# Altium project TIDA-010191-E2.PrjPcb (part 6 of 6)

## Sheet TIDA-010191-E2_USB.SchDoc: FT4232HQ_USB
size 558 x 431 mm; Date: Not shown in title block; ApprovedBy: Not shown in title block; CheckedBy: Not shown in title block; Author: Not shown in title block; CompanyName: Not shown in title block; DrawnBy: Avinash N; Engineer: Not shown in title block; Organization: Not shown in title block; Address1: Not shown in title block; Address2: Not shown in title block; Address3: Not shown in title block; Address4: Not shown in title block; DocumentNumber: 8; Revision: Use project parameter SCH_Rev; SheetNumber: 8; SheetTotal: 9; PageSetup: Record=PageOptions¦CenterHorizontal=True¦CenterVertical=True¦PrintScale=1.00¦XCorrection=1.00¦YCorrection=1.00¦PrintKind=0¦BorderSize=5000000¦LeftOffset=0¦BottomOffset=0¦Orientation=2¦PaperLength=1000¦PaperWidth=1000¦Scale=100¦PaperSource=15¦PrintQuality=600¦MediaType=1¦DitherType=10¦PaperKind=Letter¦PrintScaleMode=1
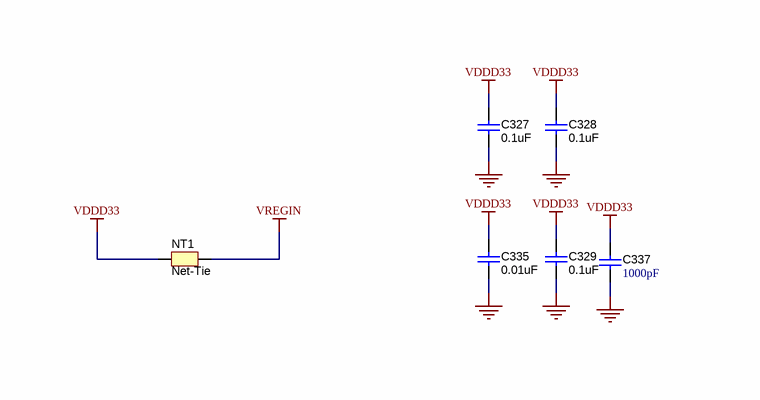
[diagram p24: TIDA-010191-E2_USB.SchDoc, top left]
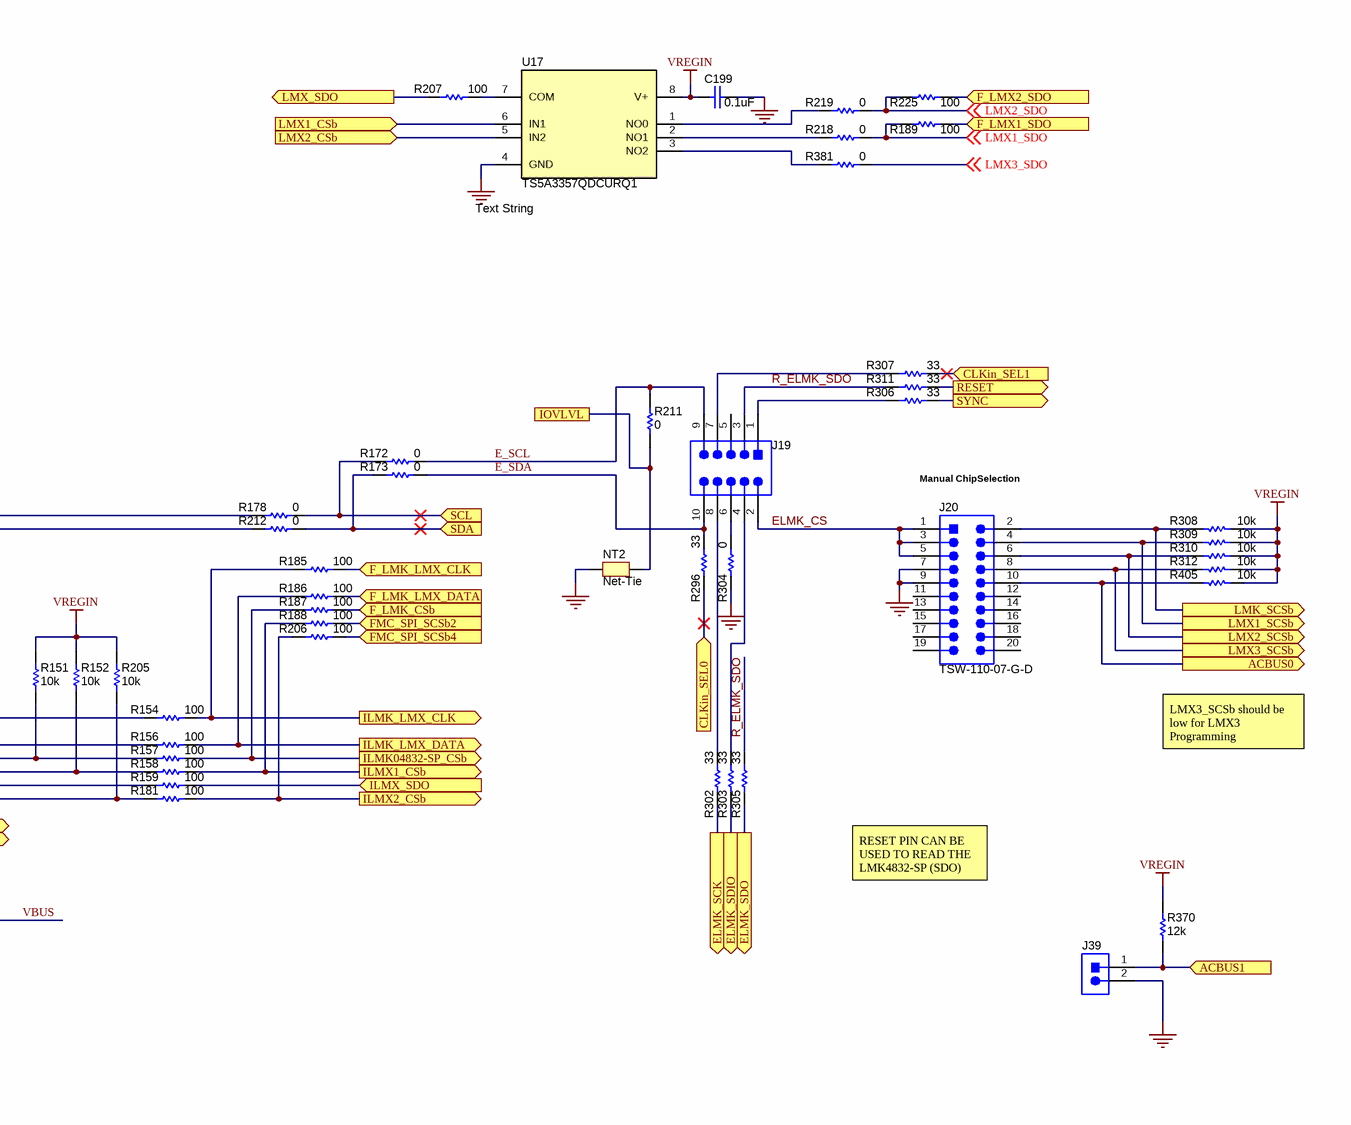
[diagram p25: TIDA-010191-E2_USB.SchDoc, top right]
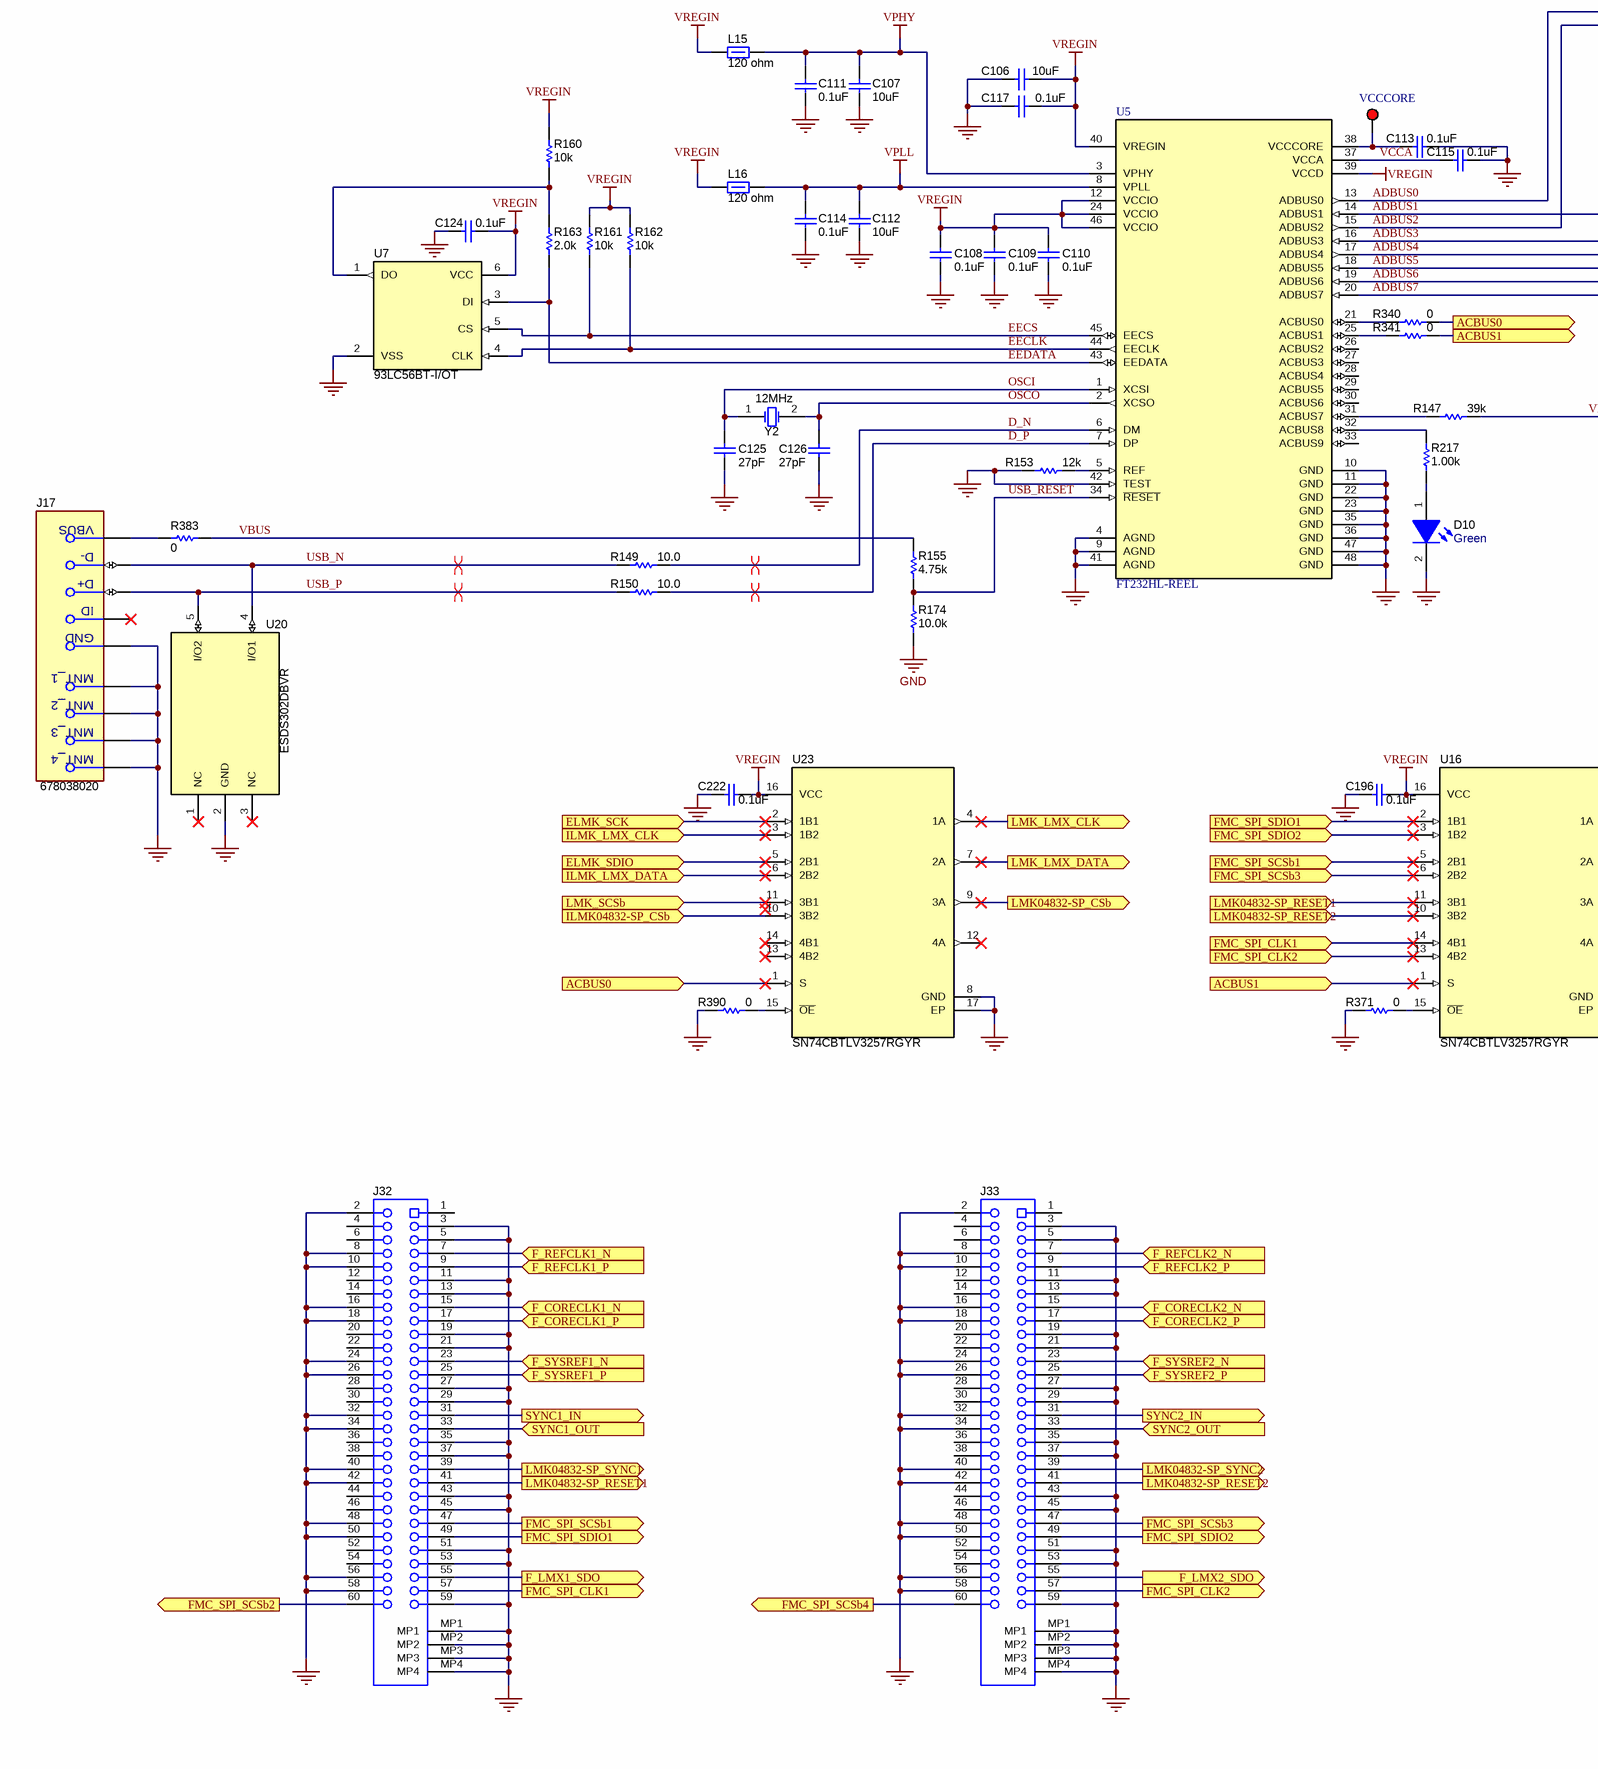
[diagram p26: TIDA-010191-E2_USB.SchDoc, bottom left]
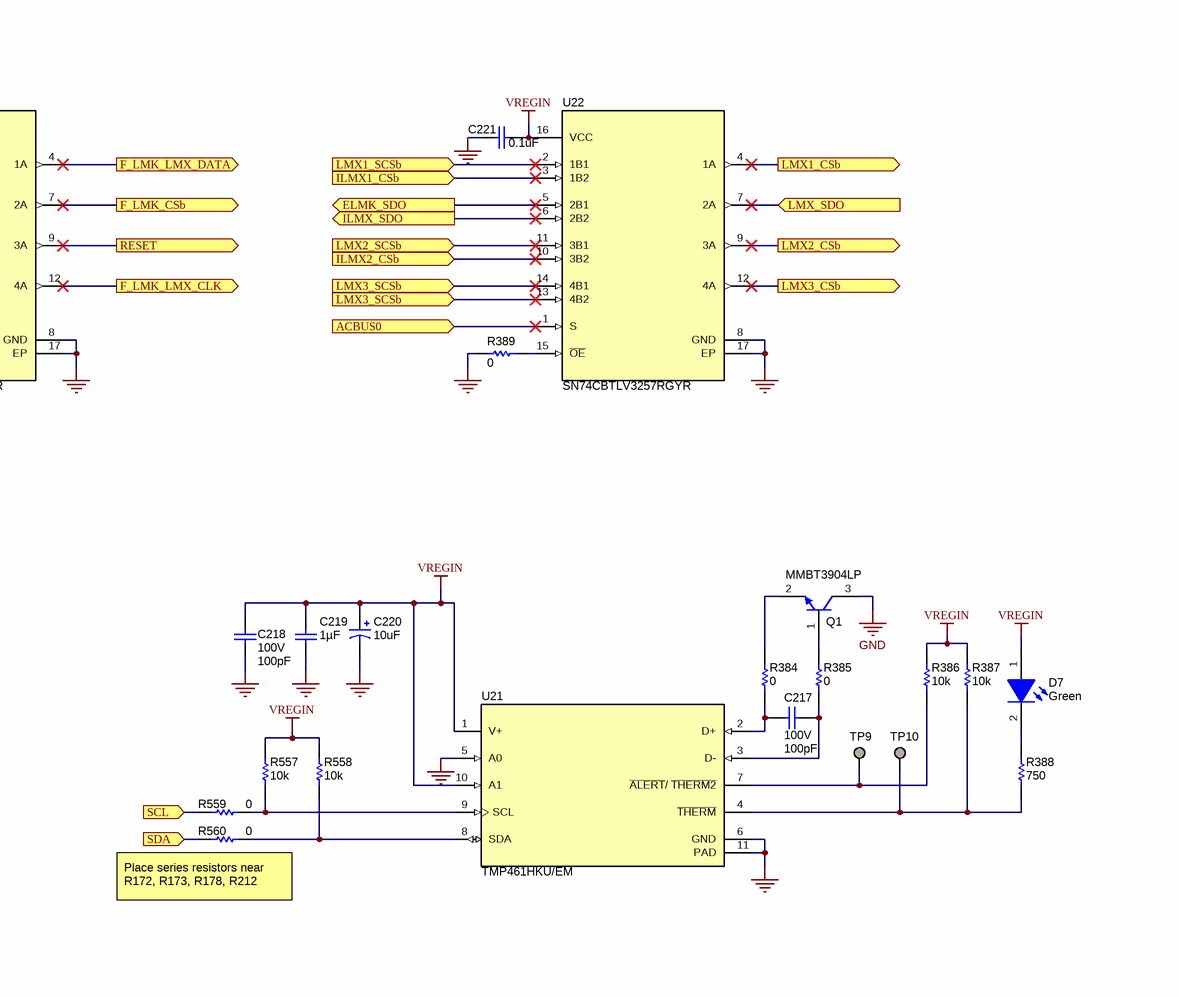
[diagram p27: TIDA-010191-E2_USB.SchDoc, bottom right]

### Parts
C106  ValueDisplayed: 10uF  [0603]  (hidden comment: CMP-0007003-5)
C107  ValueDisplayed: 10uF  [0603]  (hidden comment: CMP-0007003-5)
C108  ValueDisplayed: 0.1uF  [0603]  (hidden comment: Capacitor)
C109  ValueDisplayed: 0.1uF  [0603]  (hidden comment: Capacitor)
C110  ValueDisplayed: 0.1uF  [0603]  (hidden comment: Capacitor)
C111  ValueDisplayed: 0.1uF  [0603]  (hidden comment: Capacitor)
C112  ValueDisplayed: 10uF  [0603]  (hidden comment: CMP-0007003-5)
C113  ValueDisplayed: 0.1uF  [0603]  (hidden comment: Capacitor)
C114  ValueDisplayed: 0.1uF  [0603]  (hidden comment: Capacitor)
C115  ValueDisplayed: 0.1uF  [0603]  (hidden comment: Capacitor)
C117  ValueDisplayed: 0.1uF  [0603]  (hidden comment: Capacitor)
C124  ValueDisplayed: 0.1uF  [0603]  (hidden comment: Capacitor)
C125  ValueDisplayed: 27pF  [0603]  (hidden comment: Capacitor)
C126  ValueDisplayed: 27pF  [0603]  (hidden comment: Capacitor)
C196  value 0.1uF  [0603]  (hidden comment: C0603C104J3RACTU)
C199  ValueDisplayed: 0.1uF  [0603]  (hidden comment: Capacitor)
C217  VDC_V: 100V  ValueDisplayed: 100pF  [0603]  (hidden comment: GCM1885C2A101JA16D)
C218  VDC_V: 100V  ValueDisplayed: 100pF  [0603]  (hidden comment: GCM1885C2A101JA16D)
C219  ValueDisplayed: 1µF  [0603]  (hidden comment: 0603YD105KAT2A)
C220  ValueDisplayed: 10uF  [3528-21]  (hidden comment: 293D106X0010B2TE3)
C221  value 0.1uF  [0603]  (hidden comment: C0603C104J3RACTU)
C222  value 0.1uF  [0603]  (hidden comment: C0603C104J3RACTU)
C327  ValueDisplayed: 0.1uF  [0603]  (hidden comment: Capacitor)
C328  ValueDisplayed: 0.1uF  [0603]  (hidden comment: Capacitor)
C329  ValueDisplayed: 0.1uF  [0603]  (hidden comment: Capacitor)
C335  ValueDisplayed: 0.01uF  [0603]  (hidden comment: Capacitor)
C337  ValueDisplayed: 1000pF  [0805_HV]  (hidden comment: Capacitor)
D7  value Green  [LTST-C191_Green]  (hidden comment: LTST-C191KGKT)
D10  value Green  [LTST-C191_Green]  (hidden comment: LED)
J17  678038020  [FP-678038020_CONN_USB-MFG]
J19  CMP-0055434-2  [FCI_52601-S10-8LF]  (value not drawn)
J20  TSW-110-07-G-D  [TSW-110-07-G-D]
J32  CMP-0075524-1  [Samtec_QSH-030-01-X-D-A]  (value not drawn)
J33  CMP-0075524-1  [Samtec_QSH-030-01-X-D-A]  (value not drawn)
J39  HTSW-102-07-G-S  [Samtec_HTSW-102-07-G-S]  (value not drawn)
L15  ValueDisplayed: 120 ohm  [1206]  (hidden comment: Ferrite_Bead)
L16  ValueDisplayed: 120 ohm  [1206]  (hidden comment: Ferrite_Bead)
NT1  Net-Tie  [Net-Tie_0805_HV_NoOverlay]  (net tie, no BOM)
NT2  Net-Tie  [Net-Tie_0805_HV_NoOverlay]  (net tie, no BOM)
Q1  MMBT3904LP  [DIODES_X1-DFN1006-3]
R147  ValueDisplayed: 39k  [0603]  (hidden comment: Resistor)
R149  ValueDisplayed: 10.0  [0603]  (hidden comment: Resistor)
R150  ValueDisplayed: 10.0  [0603]  (hidden comment: Resistor)
R151  ValueDisplayed: 10k  [0603]  (hidden comment: Resistor)
R152  ValueDisplayed: 10k  [0603]  (hidden comment: Resistor)
R153  ValueDisplayed: 12k  [0603]  (hidden comment: CMP-0025711-4)
R154  ValueDisplayed: 100  [0603]  (hidden comment: CMP-0021991-4)
R155  ValueDisplayed: 4.75k  [0402]  (hidden comment: CRCW04024K75FKED)
R156  ValueDisplayed: 100  [0603]  (hidden comment: CMP-0021991-4)
R157  ValueDisplayed: 100  [0603]  (hidden comment: CMP-0021991-4)
R158  ValueDisplayed: 100  [0603]  (hidden comment: CMP-0021991-4)
R159  ValueDisplayed: 100  [0603]  (hidden comment: CMP-0021991-4)
R160  ValueDisplayed: 10k  [0603]  (hidden comment: Resistor)
R161  ValueDisplayed: 10k  [0603]  (hidden comment: Resistor)
R162  ValueDisplayed: 10k  [0603]  (hidden comment: Resistor)
R163  ValueDisplayed: 2.0k  [0603]  (hidden comment: Resistor)
R172  ValueDisplayed: 0  [0402]  (hidden comment: Resistor)
R173  ValueDisplayed: 0  [0402]  (hidden comment: Resistor)
R174  ValueDisplayed: 10.0k  [0402]  (hidden comment: CRCW040210K0FKED)
R178  ValueDisplayed: 0  [0603]  (hidden comment: Resistor)
R181  ValueDisplayed: 100  [0603]  (hidden comment: CMP-0021991-4)
R185  ValueDisplayed: 100  [0603]  (hidden comment: CMP-0021991-4)
R186  ValueDisplayed: 100  [0603]  (hidden comment: CMP-0021991-4)
R187  ValueDisplayed: 100  [0603]  (hidden comment: CMP-0021991-4)
R188  ValueDisplayed: 100  [0603]  (hidden comment: CMP-0021991-4)
R189  ValueDisplayed: 100  [0603]  (hidden comment: CMP-0021991-4)
R205  ValueDisplayed: 10k  [0603]  (hidden comment: Resistor)
R206  ValueDisplayed: 100  [0603]  (hidden comment: CMP-0021991-4)
R207  ValueDisplayed: 100  [0603]  (hidden comment: CMP-0021991-4)
R211  ValueDisplayed: 0  [0603]  (hidden comment: Resistor)
R212  ValueDisplayed: 0  [0603]  (hidden comment: Resistor)
R217  ValueDisplayed: 1.00k  [0603]  (hidden comment: Resistor)
R218  ValueDisplayed: 0  [0402]  (hidden comment: Resistor)
R219  ValueDisplayed: 0  [0402]  (hidden comment: Resistor)
R225  ValueDisplayed: 100  [0603]  (hidden comment: CMP-0021991-4)
R296  ValueDisplayed: 33  [0603]  (hidden comment: Resistor)
R302  ValueDisplayed: 33  [0603]  (hidden comment: Resistor)
R303  ValueDisplayed: 33  [0603]  (hidden comment: Resistor)
R304  ValueDisplayed: 0  [0603]  (hidden comment: Resistor)
R305  ValueDisplayed: 33  [0603]  (hidden comment: Resistor)
R306  ValueDisplayed: 33  [0603]  (hidden comment: Resistor)
R307  ValueDisplayed: 33  [0603]  (hidden comment: Resistor)
R308  ValueDisplayed: 10k  [0603]  (hidden comment: Resistor)
R309  ValueDisplayed: 10k  [0603]  (hidden comment: Resistor)
R310  ValueDisplayed: 10k  [0603]  (hidden comment: Resistor)
R311  ValueDisplayed: 33  [0603]  (hidden comment: Resistor)
R312  ValueDisplayed: 10k  [0603]  (hidden comment: Resistor)
R340  ValueDisplayed: 0  [0402]  (hidden comment: Resistor)
R341  ValueDisplayed: 0  [0402]  (hidden comment: Resistor)
R370  ValueDisplayed: 12k  [0402]  (hidden comment: Resistor)
R371  ValueDisplayed: 0  [0402]  (hidden comment: Resistor)
R381  ValueDisplayed: 0  [0402]  (hidden comment: Resistor)
R383  ValueDisplayed: 0  [0603]  (hidden comment: CRCW06030000Z0EA)
R384  ValueDisplayed: 0  [0805_HV]  (hidden comment: ERJ-6GEY0R00V)
R385  ValueDisplayed: 0  [0805_HV]  (hidden comment: ERJ-6GEY0R00V)
R386  ValueDisplayed: 10k  [0805_HV]  (hidden comment: CRCW080510K0JNEA)
R387  ValueDisplayed: 10k  [0805_HV]  (hidden comment: CRCW080510K0JNEA)
R388  ValueDisplayed: 750  [0805_HV]  (hidden comment: CRCW0805750RJNEA)
R389  ValueDisplayed: 0  [0402]  (hidden comment: CMP-0026822-3)
R390  ValueDisplayed: 0  [0402]  (hidden comment: Resistor)
R405  ValueDisplayed: 10k  [0603]  (hidden comment: Resistor)
R557  ValueDisplayed: 10k  [0805_HV]  (hidden comment: CRCW080510K0JNEA)
R558  ValueDisplayed: 10k  [0805_HV]  (hidden comment: CRCW080510K0JNEA)
R559  ValueDisplayed: 0  [0603]  (hidden comment: Resistor)
R560  ValueDisplayed: 0  [0603]  (hidden comment: Resistor)
TP9  1573-2  [Keystone1573-2]  (value not drawn)
TP10  1573-2  [Keystone1573-2]  (value not drawn)
U5  FT232HL-REEL  [LQFP-48_N]
U7  93LC56BT-I/OT  [SOT-23-6]
U16  SN74CBTLV3257RGYR  [RGY0016A]
U17  TS5A3357QDCURQ1  [DCU0008A_N]
U20  ESDS302DBVR  [DBV0005A_N]
U21  TMP461HKU/EM  [HKU0010_CUSTOM_A]
U22  SN74CBTLV3257RGYR  [RGY0016A]
U23  SN74CBTLV3257RGYR  [RGY0016A]
VCCCORE  5000  [Keystone5000]  (value not drawn)
Y2  Frequency_Fixed: 12MHz  [XTAL_ABM3]  (hidden comment: ABM3-12.000MHZ-D2Y-T)

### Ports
ACBUS0 (in), ACBUS0 (out), ACBUS1 (in), ACBUS1 (out), CLKin_SEL0 (in), CLKin_SEL1 (in), ELMK_SCK (in), ELMK_SCK (out), ELMK_SDIO (in), ELMK_SDIO (out), ELMK_SDO (out), F_CORECLK1_N (in), F_CORECLK1_P (in), F_CORECLK2_N (in), F_CORECLK2_P (in), F_LMK_CSb (in), F_LMK_CSb (out), F_LMK_LMX_CLK (in), F_LMK_LMX_CLK (out), F_LMK_LMX_DATA (in), F_LMK_LMX_DATA (out), F_LMX1_SDO (in), F_LMX1_SDO (out), F_LMX2_SDO (in), F_LMX2_SDO (out), F_REFCLK1_N (in), F_REFCLK1_P (in), F_REFCLK2_N (in), F_REFCLK2_P (in), F_SYSREF1_N (in), F_SYSREF1_P (in), F_SYSREF2_N (in), F_SYSREF2_P (in), FMC_SPI_CLK1 (in), FMC_SPI_CLK1 (out), FMC_SPI_CLK2 (in), FMC_SPI_CLK2 (out), FMC_SPI_SCSb1 (in), FMC_SPI_SCSb1 (out), FMC_SPI_SCSb2 (in), FMC_SPI_SCSb2 (out), FMC_SPI_SCSb3 (in), FMC_SPI_SCSb3 (out), FMC_SPI_SCSb4 (in), FMC_SPI_SCSb4 (out), FMC_SPI_SDIO1 (in), FMC_SPI_SDIO1 (out), FMC_SPI_SDIO2 (in), FMC_SPI_SDIO2 (out), ILMK04832-SP_CSb (in), ILMK04832-SP_CSb (out), ILMK_LMX_CLK (in), ILMK_LMX_CLK (out), ILMK_LMX_DATA (in), ILMK_LMX_DATA (out), ILMX1_CSb (in), ILMX1_CSb (out), ILMX2_CSb (in), ILMX2_CSb (out), ILMX_SDO (in), ILMX_SDO (out), IOVLVL, LMK04832-SP_CSb (out), LMK04832-SP_RESET1 (in), LMK04832-SP_RESET1 (out), LMK04832-SP_RESET2 (in), LMK04832-SP_RESET2 (out), LMK04832-SP_SYNC1 (out), LMK04832-SP_SYNC2 (out), LMK_LMX_CLK (out), LMK_LMX_DATA (out), LMK_SCSb (in), LMK_SCSb (out), LMX1_CSb (in), LMX1_CSb (out), LMX1_SCSb (in), LMX1_SCSb (out), LMX2_CSb (in), LMX2_CSb (out), LMX2_SCSb (in), LMX2_SCSb (out), LMX3_CSb (out), LMX3_SCSb (in), LMX3_SCSb (out), LMX_SDO (in), LMX_SDO (out), RESET (out), SCL (in), SDA (in), SYNC1_IN (out), SYNC1_OUT (in), SYNC2_IN (out), SYNC2_OUT (in), SYNC (out)

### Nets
GND: C106.2 C107.2 C108.2 C109.2 C110.2 C111.2 C112.2 C113.1 C114.2 C115.1 C117.2 C124.1 C125.1 C126.2 C196.2 C199.2 C218.2 C219.2 C220.2(-) C221.2 C222.2 C327.2 C328.2 C329.2 C335.2 C337.2 D10.2(K) J17.5(GND) J17.6(MNT_1) J17.7(MNT_2) J17.8(MNT_3) J17.9(MNT_4) J20.7 J20.9 J32.2 J32.3 J32.5 J32.8 J32.10 J32.11 J32.13 J32.16 J32.18 J32.19 J32.21 J32.24 J32.26 J32.27 J32.29 J32.32 J32.34 J32.35 J32.37 J32.40 J32.42 J32.43 J32.45 J32.48 J32.50 J32.51 J32.53 J32.56 J32.58 J32.59 J32.MP1 J32.MP2 J32.MP3 J32.MP4 J33.2 J33.3 J33.5 J33.8 J33.10 J33.11 J33.13 J33.16 J33.18 J33.19 J33.21 J33.24 J33.26 J33.27 J33.29 J33.32 J33.34 J33.35 J33.37 J33.40 J33.42 J33.43 J33.45 J33.48 J33.50 J33.51 J33.53 J33.56 J33.58 J33.59 J33.MP1 J33.MP2 J33.MP3 J33.MP4 J39.2 NT2.2 Q1.3(C) R153.2 R174.1 R304.1 R371.1 R389.1 R390.1 U5.4(AGND) U5.9(AGND) U5.10(GND) U5.11(GND) U5.22(GND) U5.23(GND) U5.35(GND) U5.36(GND) U5.41(AGND) U5.42(TEST) U5.47(GND) U5.48(GND) U7.2(VSS) U16.8(GND) U16.17(EP) U17.4(GND) U20.2(GND) U21.5(A0) U21.6(GND) U21.11(PAD) U22.8(GND) U22.17(EP) U23.8(GND) U23.17(EP)
VDDD33: C327.1 C328.1 C329.1 C335.1 C337.1 NT1.1
VPHY: C107.1 C111.1 L15.2 U5.3(VPHY)
VPLL: C112.1 C114.1 L16.2 U5.8(VPLL)
VREGIN: C106.1 C108.1 C109.1 C110.1 C117.1 C124.2 C196.1 C199.1 C218.1 C219.1 C220.1(+) C221.1 C222.1 D7.1(A) L15.1 L16.1 NT1.2 R151.2 R152.2 R160.2 R161.2 R162.2 R205.2 R308.1 R309.1 R310.1 R312.1 R370.2 R386.2 R387.2 R405.1 R557.2 R558.2 U5.12(VCCIO) U5.24(VCCIO) U5.39(VCCD) U5.40(VREGIN) U5.46(VCCIO) U7.6(VCC) U16.16(VCC) U17.8(V+) U21.1(V+) U21.10(A1) U22.16(VCC) U23.16(VCC)
ACBUS0: J20.10 R340.1 R405.2 U22.1(S) U23.1(S) ; port ACBUS0
ACBUS1: J39.1 R341.1 R370.1 U16.1(S) ; port ACBUS1
ADBUS0: R178.1 U5.13(ADBUS0)
ADBUS1: R154.1 U5.14(ADBUS1)
ADBUS2: R212.1 U5.15(ADBUS2)
ADBUS3: R156.1 U5.16(ADBUS3)
ADBUS4: R151.1 R157.1 U5.17(ADBUS4)
ADBUS5: R152.1 R158.1 U5.18(ADBUS5)
ADBUS6: R159.1 U5.19(ADBUS6)
ADBUS7: R181.1 R205.1 U5.20(ADBUS7)
CLKin_SEL0: R296.2 ; port CLKin_SEL0
CLKin_SEL1: R307.1 ; port CLKin_SEL1
D_N: R149.2 U5.6(DM)
D_P: R150.2 U5.7(DP)
E_SCL: J19.9 R172.2 R211.1
E_SDA: J19.10 R173.2 R296.1
EECLK: R162.1 U5.44(EECLK) U7.4(CLK)
EECS: R161.1 U5.45(EECS) U7.5(CS)
EEDATA: R163.1 U5.43(EEDATA) U7.3(DI)
ELMK_CS: J19.2 J20.1 J20.3 J20.5
ELMK_SCK: R302.1 U23.2(1B1) ; port ELMK_SCK
ELMK_SDIO: R303.1 U23.5(2B1) ; port ELMK_SDIO
ELMK_SDO: R305.1 U22.5(2B1) ; port ELMK_SDO
F_CORECLK1_N: J32.15 ; port F_CORECLK1_N
F_CORECLK1_P: J32.17 ; port F_CORECLK1_P
F_CORECLK2_N: J33.15 ; port F_CORECLK2_N
F_CORECLK2_P: J33.17 ; port F_CORECLK2_P
F_LMK_CSb: R187.2 U16.7(2A) ; port F_LMK_CSb
F_LMK_LMX_CLK: R185.2 U16.12(4A) ; port F_LMK_LMX_CLK
F_LMK_LMX_DATA: R186.2 U16.4(1A) ; port F_LMK_LMX_DATA
F_LMX1_SDO: J32.55 R189.1 ; port F_LMX1_SDO
F_LMX2_SDO: J33.55 R225.1 ; port F_LMX2_SDO
F_REFCLK1_N: J32.7 ; port F_REFCLK1_N
F_REFCLK1_P: J32.9 ; port F_REFCLK1_P
F_REFCLK2_N: J33.7 ; port F_REFCLK2_N
F_REFCLK2_P: J33.9 ; port F_REFCLK2_P
F_SYSREF1_N: J32.23 ; port F_SYSREF1_N
F_SYSREF1_P: J32.25 ; port F_SYSREF1_P
F_SYSREF2_N: J33.23 ; port F_SYSREF2_N
F_SYSREF2_P: J33.25 ; port F_SYSREF2_P
FMC_SPI_CLK1: J32.57 U16.14(4B1) ; port FMC_SPI_CLK1
FMC_SPI_CLK2: J33.57 U16.13(4B2) ; port FMC_SPI_CLK2
FMC_SPI_SCSb1: J32.47 U16.5(2B1) ; port FMC_SPI_SCSb1
FMC_SPI_SCSb2: J32.60 R188.2 ; port FMC_SPI_SCSb2
FMC_SPI_SCSb3: J33.47 U16.6(2B2) ; port FMC_SPI_SCSb3
FMC_SPI_SCSb4: J33.60 R206.2 ; port FMC_SPI_SCSb4
FMC_SPI_SDIO1: J32.49 U16.2(1B1) ; port FMC_SPI_SDIO1
FMC_SPI_SDIO2: J33.49 U16.3(1B2) ; port FMC_SPI_SDIO2
ILMK04832-SP_CSb: R157.2 R187.1 U23.10(3B2) ; port ILMK04832-SP_CSb
ILMK_LMX_CLK: R154.2 R185.1 U23.3(1B2) ; port ILMK_LMX_CLK
ILMK_LMX_DATA: R156.2 R186.1 U23.6(2B2) ; port ILMK_LMX_DATA
ILMX1_CSb: R158.2 R188.1 U22.3(1B2) ; port ILMX1_CSb
ILMX2_CSb: R181.2 R206.1 U22.10(3B2) ; port ILMX2_CSb
ILMX_SDO: R159.2 U22.6(2B2) ; port ILMX_SDO
IOVLVL: NT2.1 R211.2 ; port IOVLVL
LMK04832-SP_CSb: U23.9(3A) ; port LMK04832-SP_CSb
LMK04832-SP_RESET1: J32.41 U16.11(3B1) ; port LMK04832-SP_RESET1
LMK04832-SP_RESET2: J33.41 U16.10(3B2) ; port LMK04832-SP_RESET2
LMK04832-SP_SYNC1: J32.39 ; port LMK04832-SP_SYNC1
LMK04832-SP_SYNC2: J33.39 ; port LMK04832-SP_SYNC2
LMK_LMX_CLK: U23.4(1A) ; port LMK_LMX_CLK
LMK_LMX_DATA: U23.7(2A) ; port LMK_LMX_DATA
LMK_SCSb: J20.2 R308.2 U23.11(3B1) ; port LMK_SCSb
LMX1_CSb: U17.6(IN1) U22.4(1A) ; port LMX1_CSb
LMX1_SCSb: J20.4 R309.2 U22.2(1B1) ; port LMX1_SCSb
LMX1_SDO: R189.2 R218.2 ; off-sheet LMX1_SDO
LMX2_CSb: U17.5(IN2) U22.9(3A) ; port LMX2_CSb
LMX2_SCSb: J20.6 R310.2 U22.11(3B1) ; port LMX2_SCSb
LMX2_SDO: R219.2 R225.2 ; off-sheet LMX2_SDO
LMX3_CSb: U22.12(4A) ; port LMX3_CSb
LMX3_SCSb: J20.8 R312.2 U22.13(4B2) U22.14(4B1) ; port LMX3_SCSb
LMX3_SDO: R381.2 ; off-sheet LMX3_SDO
LMX_SDO: R207.2 U22.7(2A) ; port LMX_SDO
OSCI: C125.2 U5.1(XCSI) Y2.1(OSC1)
OSCO: C126.1 U5.2(XCSO) Y2.2(OSC2)
R_ELMK_SDO: J19.3 R305.2 R311.2
RESET: R311.1 U16.9(3A) ; port RESET
SCL: R172.1 R178.2 R559.1 ; port SCL
SDA: R173.1 R212.2 R560.1 ; port SDA
SYNC: R306.1 ; port SYNC
SYNC1_IN: J32.31 ; port SYNC1_IN
SYNC1_OUT: J32.33 ; port SYNC1_OUT
SYNC2_IN: J33.31 ; port SYNC2_IN
SYNC2_OUT: J33.33 ; port SYNC2_OUT
USB_N: J17.2(D-) R149.1 U20.4(I/O1)
USB_P: J17.3(D+) R150.1 U20.5(I/O2)
USB_RESET: R155.1 R174.2 U5.34(~{RESET})
VBUS: R147.2 R155.2 R383.2
VCCA: C115.2 U5.37(VCCA)
NetC113_2: C113.2 U5.38(VCCCORE) VCCCORE.1
NetC217_1: C217.1 R384.1 U21.2(D+)
NetC217_2: C217.2 R385.1 U21.3(D-)
NetD7_2: D7.2(K) R388.2
NetD10_1: D10.1(A) R217.1
NetJ17_1: J17.1(VBUS) R383.1
NetJ19_1: J19.1 R306.2
NetJ19_4: J19.4 R303.2
NetJ19_6: J19.6 R304.2
NetJ19_7: J19.7 R307.2
NetJ19_8: J19.8 R302.2
NetQ1_1: Q1.1(B) R385.2
NetQ1_2: Q1.2(E) R384.2
NetR147_1: R147.1 U5.31(ACBUS7)
NetR153_1: R153.1 U5.5(REF)
NetR160_1: R160.1 R163.2 U7.1(DO)
NetR207_1: R207.1 U17.7(COM)
NetR217_2: R217.2 U5.32(ACBUS8)
NetR218_1: R218.1 U17.2(NO1)
NetR219_1: R219.1 U17.1(NO0)
NetR340_2: R340.2 U5.21(ACBUS0)
NetR341_2: R341.2 U5.25(ACBUS1)
NetR371_2: R371.2 U16.15(~{OE})
NetR381_1: R381.1 U17.3(NO2)
NetR386_1: R386.1 TP9.1 U21.7(~{ALERT}/_~{THERM2})
NetR387_1: R387.1 R388.1 TP10.1 U21.4(~{THERM})
NetR389_2: R389.2 U22.15(~{OE})
NetR390_2: R390.2 U23.15(~{OE})
NetR557_1: R557.1 R559.2 U21.9(SCL)
NetR558_1: R558.1 R560.2 U21.8(SDA)

Not connected (* = marked no-connect by the designer): J17 4(ID)*; J19 5; J20 11 12 13 14 15 16 17 18 19 20; J32 1 4 6 12 14 20 22 28 30 36 38 44 46 52 54; J33 1 4 6 12 14 20 22 28 30 36 38 44 46 52 54; U5 26(ACBUS2) 27(ACBUS3) 28(ACBUS4) 29(ACBUS5) 30(ACBUS6) 33(ACBUS9); U20 1(NC)* 3(NC)*; U23 12(4A)* 13(4B2)* 14(4B1)*

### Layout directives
differential pair: D_N, D_P, USB_N, USB_P

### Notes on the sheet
- (near U17) Text String
- (near J20) Manual ChipSelection
- LMX3_SCSb should be low for LMX3 Programming
- RESET PIN CAN BE USED TO READ THE LMK4832-SP (SDO)
- (near R560) Place series resistors near R172, R173, R178, R212

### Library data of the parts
C106 C107 C112 = CMP-0007003-5: CAP, CERM, 10 uF, 10 V, +/- 20%, X5R, 0603; Manufacturer: TDK; PartNumber: C1608X5R1A106M080AC; ESR_ohm: 7.8m; IRMS_A: 1.85A; Polarized: N; TaMax_C: 85°C; TaMin_C: -55°C; VDC_V: 10V; Cap_F: 10µF; Value: 10uF; U/M: EA; Value1: 0.0078 ohm; AEC Category: Q200; SizeAreaWB_mm2: 4.68; SizeZ_mm: 1; SizeX_mm: 1.6; SizeY_mm: 0.8; SizeArea_mm2: 1.28
C108-C111 C113-C115 C117 C124 C199 = CMP-0006856-6: CAP, CERM, 0.1 uF, 25 V, +/- 5%, X7R, 0603; Manufacturer: Kemet; PartNumber: C0603C104J3RACTU; Polarized: N; TaMax_C: 125°C; TaMin_C: -55°C; VDC_V: 25V; Cap_F: 100nF; Value: 0.1uF; Value1: Unknown; U/M: EA; AEC Category: Q200; SizeArea_mm2: 1.28; SizeAreaWB_mm2: 4.68; SizeX_mm: 1.6; SizeY_mm: 0.8; SizeZ_mm: 1
C125 C126 = CMP-0007259-4: CAP, CERM, 27 pF, 100 V, +/- 5%, C0G/NP0, 0603; PartNumber: GRM1885C2A270JA01D; Manufacturer: MuRata; Polarized: N; Value: 27pF; U/M: EA; Value1: Unknown; VDC_V: 100V; TaMin_C: -55°C; TaMax_C: 125°C; SizeArea_mm2: 1.28; SizeAreaWB_mm2: 4.68; SizeX_mm: 1.6; SizeY_mm: 0.8; SizeZ_mm: 1; AEC Category: Q200
C196 C221 C222 = CMP-0006856-6: CAP, CERM, 0.1 uF, 25 V, +/- 5%, X7R, 0603; Manufacturer: Kemet; TaMin_C: -55°C; Polarized: N; SizeAreaWB_mm2: 4.68; Value1: Unknown; U/M: EA; TaMax_C: 125°C; SizeZ_mm: 1; SizeX_mm: 1.6; SizeY_mm: 0.8; Value2: 25V; SizeArea_mm2: 1.28; Cap_F: 100nF; AEC Category: Q200
C217 C218 = CMP-0007130-4: CAP, CERM, 100 pF, 100 V, +/- 5%, C0G/NP0, AEC-Q200 Grade 1, 0603; Manufacturer: MuRata; TaMin_C: -55°C; Polarized: N; SizeAreaWB_mm2: 4.68; Value1: Unknown; U/M: EA; TaMax_C: 125°C; SizeZ_mm: 1; SizeX_mm: 1.6; SizeY_mm: 0.8; SizeArea_mm2: 1.28; AEC Qualified: Y; AEC Category: Q200; Value: 100pF
C219 = CMP-0860183-1: CAP, CERM, 1 µF, 16 V,+/- 10%, X5R, 0603; Manufacturer: AVX; SizeArea_mm2: 1.28; U/M: EA; TaMax_C: 85°C; Polarized: N; Value: 1uF; AEC Category: Q200; Value2: 16V; SizeX_mm: 1.6; SizeAreaWB_mm2: 4.68; TaMin_C: -55°C; SizeZ_mm: 1; SizeY_mm: 0.8
C220 = CMP-0011510-2: CAP, TA, 10 uF, 10 V, +/- 20%, 2.5 ohm, SMD; Manufacturer: Vishay-Sprague; TaMin_C: -55°C; ESR_ohm: 2.5; Polarized: Y; SizeAreaWB_mm2: 17.1; Value1: 2.5 ohm; U/M: EA; Value: 10uF; TaMax_C: 125°C; SizeZ_mm: 2.1; SizeX_mm: 3.5; SizeY_mm: 2.8; Cap_Case: B; Value2: 10V; SizeArea_mm2: 9.8; CompType: Capacitor; Cap_F: 10µF; IRMS_A: 180mA; AEC Category: Q200
C327-C329 = CMP-0007044-5: CAP, CERM, 0.1 uF, 50 V, +/- 10%, X7R, 0603; PartNumber: C1608X7R1H104K080AA; Manufacturer: TDK; Polarized: N; Value: 0.1uF; U/M: EA; Cap_F: 100nF; ESR_ohm: 0.0296; Value1: 0.0296 ohm; VDC_V: 50V; IRMS_A: 971.99mA; TaMin_C: -55°C; TaMax_C: 125°C; SizeArea_mm2: 1.28; SizeAreaWB_mm2: 4.68; SizeX_mm: 1.6; SizeY_mm: 0.8; SizeZ_mm: 1; AEC Category: Q200
C335 = CMP-0007043-4: CAP, CERM, 0.01 uF, 50 V, +/- 10%, X7R, 0603; PartNumber: C1608X7R1H103K080AA; Manufacturer: TDK; Polarized: N; Value: 0.01uF; U/M: EA; Cap_F: 10nF; ESR_ohm: 0.0539; Value1: 0.0539 ohm; VDC_V: 50V; TaMin_C: -55°C; TaMax_C: 125°C; SizeArea_mm2: 1.28; SizeAreaWB_mm2: 4.68; SizeX_mm: 1.6; SizeY_mm: 0.8; SizeZ_mm: 1; AEC Category: Q200
C337 = CMP-0008141-3: CAP, CERM, 1000 pF, 25 V, +/- 10%, X7R, 0805; PartNumber: GRM216R71E102KA01D; Manufacturer: MuRata; Polarized: N; Value: 1000pF; U/M: EA; Cap_F: 1nF; Value1: Unknown; VDC_V: 25V; TaMin_C: -55°C; TaMax_C: 125°C; Cap_Case: 0805; SizeArea_mm2: 2.5; SizeAreaWB_mm2: 6.75; SizeX_mm: 2; SizeY_mm: 1.25; SizeZ_mm: 1.45; AEC Category: Q200; MFG_Status: TI_Obsolete
D7 = CMP-0078478-2: LED, Green, SMD; Manufacturer: Lite-On; Value2: 2V; Vr_V: 5V; Ir_A: 10µA; Value1: 0.075W; Tjmax_C: 85°C; Green_Lifecycle: Not Set; Angle: 130; Type: AlInGaP; Power_TotalModule: 75mW; Io_A: 30mA; Green_REACh: Incomplete
D10 = CMP-0002891-3: LED, Green, SMD; PartNumber: LTST-C191TGKT; Manufacturer: Lite-On; Type: InGaN; Vf_V: 3.2V; Io_A: 20mA; Value1: W
J17 = CMP-0088148-1: MOLEX 67803-8020 MINI USB, 2.0 OTG TYPE AB, RCPT, TH; Current_A: 1A; Shrouded: true; Voltage_V: 30V; ContactFinish: Gold,Nickel
J19 = CMP-0055434-2: Header (shrouded), 100mil, 5x2, Gold, SMT; PartNumber: 52601-S10-8LF; Manufacturer: FCI; Green_Lifecycle: Active; Green_REACh: Passed
J20 = CMP-0075421-2: Header, 100mil, 10x2, Gold, TH; Manufacturer: Samtec; Pitch_mm: 2.54; Cert_VDE: N; Gender: Male; Cert_CSA: Y; Voltage_V: 550V; Green_REACh: Passed; Current_A: 6.3A; Green_Lifecycle: Active; Row_Count: 2
J32 J33 = CMP-0075524-1: Receptacle, 0.5 mm, 30x2, Gold, TH; PartNumber: QSH-030-01-L-D-A; Manufacturer: Samtec; Pitch_mm: 0.5; Gender: Female; Shrouded: N; Row_Count: 2; RowSpacing_mm: 5.73; Green_REACh: Passed; CT: False; Green_Lifecycle: Active
J39 = CMP-0075483-1: Header, 100mil, 2x1, Gold, TH; Manufacturer: Samtec; Green_REACh: Passed; CT: False; Green_Lifecycle: Active; CNHeader: True
L15 L16 = CMP-0003365-1: Ferrite Bead, 120 ohm @ 100 MHz, 3.5 A, 1206; PartNumber: BLM31PG121SN1L; Manufacturer: MuRata; Value: 120 ohm; Imax_A: 3.5A; DCR_ohm: 0.02; Value1: 0.02 ohm; SizeAreaWB_mm2: 10.92; SizeArea_mm2: 5.12; SizeX_mm: 3.2; SizeY_mm: 1.6; SizeZ_mm: 1.35; ZTyp@100MHz_Ohm: 120
NT1 NT2 = CMP-0078142-5: Single point connection between nets.
Q1 = CMP-0000409-2: Transistor, NPN, 40 V, 0.2 A, 3-UFDFN; Manufacturer: Diodes Inc.; TaMax_C: 150°C; Value2: 400; Value1: 0.2 A; Vcesat1_V: 300mV; SizeX_mm: 1; SizeY_mm: 0.6; TaMin_C: -55°C; IcRated_A: 200mA; CompType: BJT; SizeZ_mm: 0.53; Value: 40 V; Vceo_V: 40V; PNP: 0; AEC Category: Q101; SizeAreaWB_mm2: 3.2; U/M: EA
R147 = CMP-0025794-4: RES, 39 k, 5%, 0.1 W, AEC-Q200 Grade 0, 0603; PartNumber: CRCW060339K0JNEA; Manufacturer: Vishay-Dale; Value: 39k; Value_Code: 39k0; Power_W: 100mW; Value2: 0.1W; VDC_V: 75V; TempCo: 200 ppm/C; SizeArea_mm2: 1.28; SizeX_mm: 1.6; SizeY_mm: 0.8; SizeZ_mm: 1; EIA_Code: E24; AEC Category: Q200; AEC Qualified: Y; AEC Grade: 0
R149 R150 = CMP-0022004-4: RES, 10.0, 1%, 0.25 W, AEC-Q200 Grade 0, 0603; PartNumber: CRCW060310R0FKEAHP; Manufacturer: Vishay-Dale; Value: 10.0; Res_ohm: 10; Value_Code: 10R0; Power_W: 250mW; Value2: 0.25W; VDC_V: 75V; TempCo: 100 ppm/C; SizeArea_mm2: 1.28; SizeX_mm: 1.6; SizeY_mm: 0.8; SizeZ_mm: 1; EIA_Code: E96; AEC Category: Q200; AEC Qualified: Y; AEC Grade: 0
R151 R152 R160-R162 R205 R308-R310 R312 R405 = CMP-0025701-4: RES, 10 k, 5%, 0.1 W, AEC-Q200 Grade 0, 0603; PartNumber: CRCW060310K0JNEA; Manufacturer: Vishay-Dale; Value: 10k; Value_Code: 10k0; Power_W: 100mW; Value2: 0.1W; VDC_V: 75V; TempCo: 200 ppm/C; SizeArea_mm2: 1.28; SizeX_mm: 1.6; SizeY_mm: 0.8; SizeZ_mm: 1; EIA_Code: E24; AEC Category: Q200; AEC Qualified: Y; AEC Grade: 0
R153 = CMP-0025711-4: RES, 12 k, 5%, 0.1 W, AEC-Q200 Grade 0, 0603; Manufacturer: Vishay-Dale; PartNumber: CRCW060312K0JNEA; VDC_V: 75V; Power_W: 100mW; Value: 12k; Value_Code: 12k0; Value2: 0.1W; EIA_Code: E24; TempCo: 200 ppm/C; SizeX_mm: 1.6; SizeY_mm: 0.8; SizeZ_mm: 1; SizeArea_mm2: 1.28; AEC Qualified: Y; AEC Category: Q200; AEC Grade: 0
R154 R156-R159 R181 R185-R188 R206 = CMP-0021991-4: RES, 100, 1%, 0.1 W, AEC-Q200 Grade 0, 0603; PartNumber: CRCW0603100RFKEA; Manufacturer: Vishay-Dale; Value: 100; Value_Code: 100R; Power_W: 100mW; Value2: 0.1W; VDC_V: 75V; TempCo: 100 ppm/C; SizeArea_mm2: 1.28; SizeX_mm: 1.6; SizeY_mm: 0.8; SizeZ_mm: 1; EIA_Code: E96; AEC Category: Q200; AEC Qualified: Y; AEC Grade: 0
R155 = CMP-0026412-2: RES, 4.75 k, 1%, 0.063 W, AEC-Q200 Grade 0, 0402; Manufacturer: Vishay-Dale; Power_W: 63mW; TempCo: 100 ppm/C; Value_Code: 4k75; Value: 4.75k; EIA_Code: E96; SizeX_mm: 1; SizeY_mm: 0.5; SizeZ_mm: 0.6; Value2: 0.063W; AEC Qualified: Y; VDC_V: 50V; AEC Category: Q200; AEC Grade: 0
R163 = CMP-0025768-4: RES, 2.0 k, 5%, 0.1 W, AEC-Q200 Grade 0, 0603; PartNumber: CRCW06032K00JNEA; Manufacturer: Vishay-Dale; Value: 2.0k; Res_ohm: 2k; Value_Code: 2k00; Power_W: 100mW; Value2: 0.1W; VDC_V: 75V; TempCo: 200 ppm/C; SizeArea_mm2: 1.28; SizeX_mm: 1.6; SizeY_mm: 0.8; SizeZ_mm: 1; EIA_Code: E24; AEC Category: Q200; AEC Qualified: Y; AEC Grade: 0
R172 R173 R218 R219 R371 R381 R389 R390 = CMP-0026822-3: RES, 0, 5%, 0.063 W, AEC-Q200 Grade 0, 0402; PartNumber: CRCW04020000Z0ED; Manufacturer: Vishay-Dale; Value: 0; Value_Code: 0000; Power_W: 63mW; Value2: 0.063W; VDC_V: 50V; TempCo: 200 ppm/C; SizeArea_mm2: 0.5; SizeX_mm: 1; SizeZ_mm: 0.6; EIA_Code: E24; AEC Category: Q200; AEC Qualified: Y
R174 = CMP-0025958-3: RES, 10.0 k, 1%, 0.063 W, AEC-Q200 Grade 0, 0402; Manufacturer: Vishay-Dale; Power_W: 63mW; TempCo: 100 ppm/C; Value_Code: 10k0; Value: 10.0k; EIA_Code: E96; Res_ohm: 10k; SizeX_mm: 1; SizeY_mm: 0.5; SizeZ_mm: 0.6; Value2: 0.063W; AEC Qualified: Y; VDC_V: 50V; AEC Category: Q200; AEC Grade: 0
R178 R211 R212 R304 R559 R560 = CMP-0025697-4: RES, 0, 5%, 0.1 W, AEC-Q200 Grade 0, 0603; PartNumber: CRCW06030000Z0EA; Manufacturer: Vishay-Dale; Value: 0; Value_Code: 0000; Power_W: 100mW; Value2: 0.1W; VDC_V: 75V; TempCo: 200 ppm/C; SizeArea_mm2: 1.28; SizeX_mm: 1.6; SizeY_mm: 0.8; SizeZ_mm: 1; EIA_Code: E24; AEC Category: Q200; AEC Qualified: Y
R189 R207 R225 = CMP-0021991-4: RES, 100, 1%, 0.1 W, AEC-Q200 Grade 0, 0603; Manufacturer: Vishay-Dale; PartNumber: CRCW0603100RFKEA; VDC_V: 75V; Power_W: 100mW; Value: 100; Value_Code: 100R; Value2: 0.1W; EIA_Code: E96; TempCo: 100 ppm/C; SizeArea_mm2: 1.28; SizeX_mm: 1.6; SizeY_mm: 0.8; SizeZ_mm: 1; AEC Category: Q200; AEC Qualified: Y; AEC Grade: 0
R217 = CMP-0022109-5: RES, 1.00 k, 1%, 0.1 W, AEC-Q200 Grade 0, 0603; PartNumber: CRCW06031K00FKEA; Manufacturer: Vishay-Dale; Value: 1.00k; Res_ohm: 1k; Value_Code: 1k00; Power_W: 100mW; Value2: 0.1W; VDC_V: 75V; TempCo: 100 ppm/C; SizeArea_mm2: 1.28; SizeX_mm: 1.6; SizeY_mm: 0.8; SizeZ_mm: 1; EIA_Code: E96; AEC Category: Q200; AEC Qualified: Y; AEC Grade: 0
R296 R302 R303 R305-R307 R311 = CMP-0025787-4: RES, 33, 5%, 0.1 W, AEC-Q200 Grade 0, 0603; PartNumber: CRCW060333R0JNEA; Manufacturer: Vishay-Dale; Value: 33; Value_Code: 33R0; Power_W: 100mW; Value2: 0.1W; VDC_V: 75V; TempCo: 200 ppm/C; SizeArea_mm2: 1.28; SizeX_mm: 1.6; SizeY_mm: 0.8; SizeZ_mm: 1; EIA_Code: E24; AEC Category: Q200; AEC Qualified: Y; AEC Grade: 0
R340 R341 = CMP-0026822-3: RES, 0, 5%, 0.063 W, AEC-Q200 Grade 0, 0402; Manufacturer: Vishay-Dale; PartNumber: CRCW04020000Z0ED; VDC_V: 50V; Power_W: 63mW; Value: 0; Value_Code: 0000; Value2: 0.063W; EIA_Code: E24; TempCo: 200 ppm/C; SizeArea_mm2: 0.5; SizeX_mm: 1; SizeZ_mm: 0.6; AEC Category: Q200; AEC Qualified: Y
R370 = CMP-0026834-3: RES, 12 k, 5%, 0.063 W, AEC-Q200 Grade 0, 0402; PartNumber: CRCW040212K0JNED; Manufacturer: Vishay-Dale; Value: 12k; Value_Code: 12k0; Power_W: 63mW; Value2: 0.063W; VDC_V: 50V; TempCo: 200 ppm/C; EIA_Code: E24; AEC Category: Q200; AEC Qualified: Y; AEC Grade: 0; SizeArea_mm2: 0.5; SizeX_mm: 1; SizeZ_mm: 0.6
R383 = CMP-0025697-4: RES, 0, 5%, 0.1 W, AEC-Q200 Grade 0, 0603; Manufacturer: Vishay-Dale; Power_W: 100mW; TempCo: 200 ppm/C; Value_Code: 0000; Value: 0; EIA_Code: E24; SizeX_mm: 1.6; SizeY_mm: 0.8; SizeZ_mm: 1; Value2: 0.1W; SizeArea_mm2: 1.28; AEC Qualified: Y; VDC_V: 75V; AEC Category: Q200
R384 R385 = CMP-0020616-3: RES, 0, 5%, 0.125 W, AEC-Q200 Grade 0, 0805; Manufacturer: Panasonic; Power_W: 125mW; TempCo: 600 ppm/C; Value_Code: 0000; Value: 0; EIA_Code: E24; SizeX_mm: 2; SizeY_mm: 1.25; SizeZ_mm: 1.45; Value2: 0.125W; SizeArea_mm2: 2.5; AEC Qualified: Y; VDC_V: 150V; AEC Category: Q200; SizeAreaWB_mm2: 6.75
R386 R387 R557 R558 = CMP-0020446-3: RES, 10 k, 5%, 0.125 W, AEC-Q200 Grade 0, 0805; Manufacturer: Vishay-Dale; Power_W: 125mW; TempCo: 200 ppm/C; Value_Code: 10k0; Value: 10k; EIA_Code: E24; SizeX_mm: 2; SizeY_mm: 1.25; SizeZ_mm: 1.45; Value2: 0.125W; SizeArea_mm2: 2.5; AEC Qualified: Y; VDC_V: 150V; AEC Category: Q200; AEC Grade: 0
R388 = CMP-0020593-3: RES, 750, 5%, 0.125 W, AEC-Q200 Grade 0, 0805; Manufacturer: Vishay-Dale; Power_W: 125mW; TempCo: 200 ppm/C; Value_Code: 750R; Value: 750; EIA_Code: E24; SizeX_mm: 2; SizeY_mm: 1.25; SizeZ_mm: 1.45; Value2: 0.125W; SizeArea_mm2: 2.5; AEC Qualified: Y; VDC_V: 150V; AEC Category: Q200; AEC Grade: 0
TP9 TP10 = CMP-0055119-1: Terminal, Turret, TH, Double; Manufacturer: Keystone; CompType: Turret Terminal; CT: FALSE; Green_REACh: Passed; Green_Lifecycle: Active
U5 = FT232HL-REEL: Single Channel Hi-Speed USB to Multipurpose UART/FIFO IC, LQFP-48; Manufacturer: FTDI; SymbolCreator: Altium
U7 = CMP-0005251-2: 2K Microwire Compatible Serial EEPROM, SOT-23-6; Manufacturer: Microchip; SizeAreaWB_mm2: 14.82; SizeArea_mm2: 8.12; SizeX_mm: 2.9; SizeY_mm: 2.8; SizeZ_mm: 1.15
U16 U22 U23 = CMP-0066254-2: Low-Voltage 4-Bit 1-Of-2 FET Multiplexer/Demultiplexer, RGY0016A (VQFN-16); Alternate Manufacturer: Texas Instruments; Alternate Manufacturer: None; Green_Lifecycle: Active; SizeAreaWB_mm2: 22.5; Green_REACh: Passed; U/M: EA; SizeZ_mm: 1.0; SizeX_mm: 3.5; SizeY_mm: 4.0; SizeArea_mm2: 14.0; CompType: IC
U17 = CMP-0860295-1: Automotive Catalog Single 5-Ohm SP3T Analog Switch 5-V/3.3-V 3:1 Analog Multiplexer/Demultiplexer, DCU0008A (VSSOP-8); Alternate Manufacturer: Texas Instruments; CompType: IC; SizeArea_mm2: 6.4; AEC Category: Q200; SizeZ_mm: 0.9; SizeX_mm: 3.2; SizeY_mm: 2; AEC Qualified: Y; SizeAreaWB_mm2: 12.6
U20 = CMP-0085632-1: 3.6V Data-Line Surge and 30kV ESD Protection Diode Array, DBV0005A (SOT-23-5); Manufacturer: Texas Instruments; Alternate Manufacturer: None; AEC Qualified: N; AEC Category: Q200; SizeZ_mm: 1.45; CompType: IC; Rating: Catalog; SizeX_mm: 2.8; SizeY_mm: 2.9; SizeArea_mm2: 8.12; SizeAreaWB_mm2: 14.82
U21 = CMP-0077675-3: Space Grade High-Accuracy Remote and Local Temperature Sensor with Pin-Programmable Bus Address, HKU0010A (CFP-10); Manufacturer: Texas Instruments; Alternate Manufacturer: None; CompType: IC; SizeZ_mm: 2.59; AEC Qualified: N; AEC Category: Q200
VCCCORE = CMP-0055137-2: Test Point, Miniature, Red, TH; Manufacturer: Keystone Electronics; ContactFinish: Silver; CNHeader: FALSE; CT: TRUE; Green_Lifecycle: Active; Green_REACh: Passed
Y2 = CMP-0004616-3: Crystal, 12 MHz, 18 pF, SMD; Manufacturer: Abracon Corporation; TaMin_C: -40°C; TaMax_C: 85°C; Frequency Stability: +/-30ppm

## Sheet TIDA-010191-E2_Hardware.SchDoc
size 558 x 431 mm; Date: Not shown in title block; ApprovedBy: Not shown in title block; CheckedBy: Not shown in title block; Author: Not shown in title block; CompanyName: Not shown in title block; DrawnBy: Avinash N; Engineer: Not shown in title block; Organization: Not shown in title block; Address1: Not shown in title block; Address2: Not shown in title block; Address3: Not shown in title block; Address4: Not shown in title block; DocumentNumber: 9; Revision: Use project parameter SCH_Rev; SheetNumber: 9; SheetTotal: 9; PageSetup: Record=PageOptions¦CenterHorizontal=True¦CenterVertical=True¦PrintScale=1.00¦XCorrection=1.00¦YCorrection=1.00¦PrintKind=0¦BorderSize=5000000¦LeftOffset=0¦BottomOffset=0¦Orientation=2¦PaperLength=1000¦PaperWidth=1000¦Scale=100¦PaperSource=15¦PrintQuality=600¦MediaType=1¦DitherType=10¦PaperKind=Letter¦PrintScaleMode=1
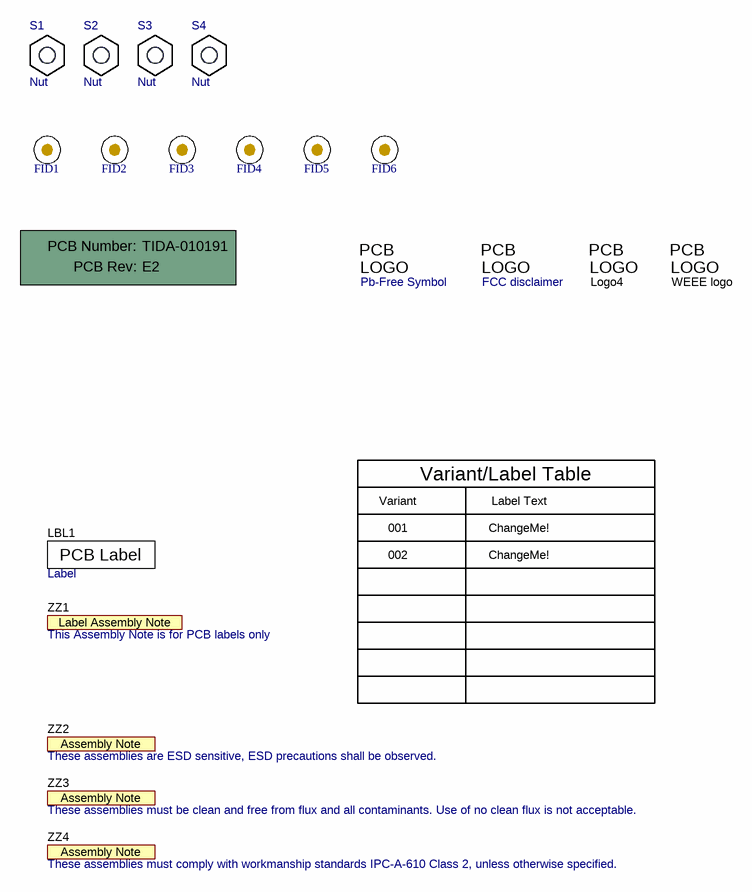
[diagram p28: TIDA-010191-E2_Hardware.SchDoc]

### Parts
!PCB1  Printed Circuit Board  (value not drawn)  (mechanical)
FID1  Fiducial  [Fiducial10-20]  (value not drawn)
FID2  Fiducial  [Fiducial10-20]  (value not drawn)
FID3  Fiducial  [Fiducial10-20]  (value not drawn)
FID4  Fiducial  [Fiducial10-20]  (value not drawn)
FID5  Fiducial  [Fiducial10-20]  (value not drawn)
FID6  Fiducial  [Fiducial10-20]  (value not drawn)
LBL1  Label  [Label_650x200]
Logo1  Pb-Free Symbol  [Pb-Free_Overlay_Small]  (no BOM)
Logo2  FCC disclaimer  [FCC_disclaimer]  (no BOM)
Logo3  WEEE logo  [WEEE_Minimum]  (no BOM)
Logo4  ESD Susceptible  [ESD_Overlay_Small]  (value not drawn)  (no BOM)
S1  Nut  [TCBS-6-01]
S2  Nut  [TCBS-6-01]
S3  Nut  [TCBS-6-01]
S4  Nut  [TCBS-6-01]
ZZ1  This Assembly Note is for PCB labels only  [AssemblyNoteLabel]  (no BOM)
ZZ2  These assemblies are ESD sensitive, ESD precautions shall be observed.  [AssemblyNote]  (no BOM)
ZZ3  These assemblies must be clean and free from flux and all contaminants. Use of no clean flux is not acceptable.  [AssemblyNote]  (no BOM)
ZZ4  These assemblies must comply with workmanship standards IPC-A-610 Class 2, unless otherwise specified.  [AssemblyNote]  (no BOM)

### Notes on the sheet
- Variant
- 001
- Variant/Label Table
- Label Text
- ChangeMe!
- 002

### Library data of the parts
!PCB1 = CMP-0003618-2: Manufacturer: Any; PartNumber: TIDA-010191
FID1-FID6 = CMP-0077181-1: Fiducial mark.  There is nothing to buy or mount.
LBL1 = CMP-0003625-1: Thermal Transfer Printable Labels, 0.650" W x 0.200" H - 10,000 per roll; Manufacturer: Brady; PartNumber: THT-14-423-10; Note: Size: 0.65" x 0.20 "
Logo1 = CMP-0074839-1: SymbolCreator: a0412235
Logo2 = CMP-0074847-1: FCC_disclaimer
Logo3 = CMP-0074769-1
Logo4 = CMP-0074840-1: ESD Susceptible Symbol; SymbolCreator: a0412235; Lib Reference: ESD_Susceptible
S1-S4 = CMP-0003647-1: HEX STANDOFF SPACER, 9.53 mm; Manufacturer: Richco Plastics
ZZ1 = CMP-0003616-3
ZZ2 = CMP-0077236-1
ZZ3 = CMP-0077237-1
ZZ4 = CMP-0077238-1

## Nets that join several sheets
+3.3V_CDCM7005: TIDA-010191-E2_CDCLVP111 (L17.1), TIDA-010191-E2_Power-Supply_2 (6 pins)
+3.3V_LMXRF: TIDA-010191-E2_LMX2615 (6 pins), TIDA-010191-E2_LMX2615_LO (L21.1 L22.1 R372.1), TIDA-010191-E2_Power-Supply_2 (6 pins)
+3.3V_VCO: TIDA-010191-E2_LMK04832 (J8.2), TIDA-010191-E2_CDCLVP111 (J16.2 R43.2 R44.2 R51.1), TIDA-010191-E2_Power-Supply_2 (6 pins)
+3.3VLMK: TIDA-010191-E2_LMK04832 (17 pins), TIDA-010191-E2_CDCLVP111 (R177.1 R179.1 R198.1 R199.1), TIDA-010191-E2_Power-Supply_2 (6 pins)
GND: TIDA-010191-E2_LMK04832 (140 pins), TIDA-010191-E2_CDCLVP111 (61 pins), TIDA-010191-E2_LMX2615 (182 pins), TIDA-010191-E2_LMX2615_LO (132 pins), TIDA-010191-E2_Power-Supply_1 (92 pins), TIDA-010191-E2_Power-Supply_2 (114 pins), TIDA-010191-E2_USB (135 pins)
P3V3_LMX: TIDA-010191-E2_LMX2615 (24 pins), TIDA-010191-E2_LMX2615_LO (12 pins), TIDA-010191-E2_Power-Supply_2 (6 pins)
P3V8: TIDA-010191-E2_Power-Supply_1 (6 pins), TIDA-010191-E2_Power-Supply_2 (34 pins)
P4V5: TIDA-010191-E2_LMK04832 (8 pins), TIDA-010191-E2_LMX2615_LO (8 pins), TIDA-010191-E2_Power-Supply_2 (12 pins)
P5V0: TIDA-010191-E2_Power-Supply_1 (19 pins), TIDA-010191-E2_Power-Supply_2 (12 pins)
P5V0*: TIDA-010191-E2_Power-Supply_1 (9 pins), TIDA-010191-E2_Power-Supply_2 (5 pins)
VDDD33: TIDA-010191-E2_LMK04832 (C2.1 U14.5), TIDA-010191-E2_Power-Supply_2 (6 pins), TIDA-010191-E2_USB (6 pins)
VIN_P5V0_Redundant: TIDA-010191-E2_Power-Supply_1 (18 pins), TIDA-010191-E2_Power-Supply_2 (R544.2)
CLKin_SEL0: TIDA-010191-E2_LMK04832 (R78.1 U1.58), TIDA-010191-E2_USB (R296.2)
CLKin_SEL1: TIDA-010191-E2_LMK04832 (R77.1 U1.59), TIDA-010191-E2_USB (R307.1)
DCLKout12_LMK_N: TIDA-010191-E2_LMK04832 (R130.1), TIDA-010191-E2_LMX2615_LO (R229.2)
DCLKout12_LMK_P: TIDA-010191-E2_LMK04832 (R126.1), TIDA-010191-E2_LMX2615_LO (R223.2)
F_CORECLK1_N: TIDA-010191-E2_LMK04832 (R70.2), TIDA-010191-E2_USB (J32.15)
F_CORECLK1_P: TIDA-010191-E2_LMK04832 (R182.2), TIDA-010191-E2_USB (J32.17)
F_CORECLK2_N: TIDA-010191-E2_LMK04832 (R183.2), TIDA-010191-E2_USB (J33.15)
F_CORECLK2_P: TIDA-010191-E2_LMK04832 (R184.2), TIDA-010191-E2_USB (J33.17)
F_REFCLK1_N: TIDA-010191-E2_LMK04832 (R4.2), TIDA-010191-E2_USB (J32.7)
F_REFCLK1_P: TIDA-010191-E2_LMK04832 (R7.2), TIDA-010191-E2_USB (J32.9)
F_REFCLK2_N: TIDA-010191-E2_LMK04832 (R63.1), TIDA-010191-E2_USB (J33.7)
F_REFCLK2_P: TIDA-010191-E2_LMK04832 (R62.1), TIDA-010191-E2_USB (J33.9)
F_SYSREF1_N: TIDA-010191-E2_LMK04832 (R19.2), TIDA-010191-E2_USB (J32.23)
F_SYSREF1_P: TIDA-010191-E2_LMK04832 (R20.2), TIDA-010191-E2_USB (J32.25)
F_SYSREF2_N: TIDA-010191-E2_LMK04832 (R55.2), TIDA-010191-E2_USB (J33.23)
F_SYSREF2_P: TIDA-010191-E2_LMK04832 (R57.2), TIDA-010191-E2_USB (J33.25)
IOVLVL: TIDA-010191-E2_LMK04832 (R335.1 U1.7), TIDA-010191-E2_USB (NT2.1 R211.2)
LMK04832-SP_CSb: TIDA-010191-E2_LMK04832 (C18.2 U1.18), TIDA-010191-E2_USB (U23.9)
LMK04832-SP_SYNC1: TIDA-010191-E2_LMK04832 (R200.1), TIDA-010191-E2_USB (J32.39)
LMK04832-SP_SYNC2: TIDA-010191-E2_LMK04832 (R202.1), TIDA-010191-E2_USB (J33.39)
LMK_LMX_CLK: TIDA-010191-E2_LMK04832 (C20.2 U1.19), TIDA-010191-E2_USB (U23.4)
LMK_LMX_CLK: TIDA-010191-E2_LMX2615 (U3.26 U4.26), TIDA-010191-E2_LMX2615_LO (U10.26)
LMK_LMX_DATA: TIDA-010191-E2_LMK04832 (C21.2 U1.20), TIDA-010191-E2_USB (U23.7)
LMK_LMX_DATA: TIDA-010191-E2_LMX2615 (U3.27 U4.27), TIDA-010191-E2_LMX2615_LO (U10.27)
LMK_OSCin_N: TIDA-010191-E2_LMK04832 (U1.44), TIDA-010191-E2_CDCLVP111 (R443.2)
LMK_OSCin_P: TIDA-010191-E2_LMK04832 (U1.43), TIDA-010191-E2_CDCLVP111 (R441.2)
LMK_VCXO: TIDA-010191-E2_LMK04832 (C87.2), TIDA-010191-E2_CDCLVP111 (C12.1 R39.2 R362.1)
LMX1_SDO: TIDA-010191-E2_LMX2615 (R102.2), TIDA-010191-E2_USB (R189.2 R218.2)
LMX2_SDO: TIDA-010191-E2_LMX2615 (R313.2), TIDA-010191-E2_USB (R219.2 R225.2)
LMX3_SDO: TIDA-010191-E2_LMX2615_LO (R279.2), TIDA-010191-E2_USB (R381.2)
LMX2615-SP_1_REF_N: TIDA-010191-E2_CDCLVP111 (R471.2), TIDA-010191-E2_LMX2615 (R243.2)
LMX2615-SP_1_REF_P: TIDA-010191-E2_CDCLVP111 (R473.2), TIDA-010191-E2_LMX2615 (R239.2)
LMX2615-SP_2_REF_N: TIDA-010191-E2_CDCLVP111 (R463.2), TIDA-010191-E2_LMX2615 (R352.2)
LMX2615-SP_2_REF_P: TIDA-010191-E2_CDCLVP111 (R461.2), TIDA-010191-E2_LMX2615 (R331.2)
LMX2615-SP_3_REF_N: TIDA-010191-E2_CDCLVP111 (R453.2), TIDA-010191-E2_LMX2615_LO (R319.2)
LMX2615-SP_3_REF_P: TIDA-010191-E2_CDCLVP111 (R451.2), TIDA-010191-E2_LMX2615_LO (R272.2)
PWRGD: TIDA-010191-E2_Power-Supply_1 (U25.20), TIDA-010191-E2_Power-Supply_2 (5 pins)
RESET: TIDA-010191-E2_LMK04832 (C184.1 R35.2 R343.1 U1.5), TIDA-010191-E2_USB (R311.1 U16.9)
SCL: TIDA-010191-E2_CDCLVP111 (R44.1 U2.8), TIDA-010191-E2_USB (R172.1 R178.2 R559.1)
SDA: TIDA-010191-E2_CDCLVP111 (R43.1 U2.7), TIDA-010191-E2_USB (R173.1 R212.2 R560.1)
SDCLKout13_LMK_N: TIDA-010191-E2_LMK04832 (R136.1), TIDA-010191-E2_LMX2615_LO (R484.2)
SDCLKout13_LMK_P: TIDA-010191-E2_LMK04832 (R135.1), TIDA-010191-E2_LMX2615_LO (R482.2)
SYNC: TIDA-010191-E2_LMK04832 (7 pins), TIDA-010191-E2_USB (R306.1)
SYNC1_IN: TIDA-010191-E2_LMK04832 (R192.1), TIDA-010191-E2_USB (J32.31)
SYNC1_OUT: TIDA-010191-E2_LMK04832 (R196.1), TIDA-010191-E2_USB (J32.33)
SYNC2_IN: TIDA-010191-E2_LMK04832 (R194.1), TIDA-010191-E2_USB (J33.31)
SYNC2_OUT: TIDA-010191-E2_LMK04832 (R197.2), TIDA-010191-E2_USB (J33.33)

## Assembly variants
001: not fitted C79 C80 C87 C90 C91 C135 C136 C137 C264 C349 C350 C352 C354 FID1 FID2 FID3 FID4 FID5 FID6 R3 R6 R34 R35 R40 R54 R56 R68 R71 R72 R73 R75 R81 R84 R92 R106 R108 R109 R110 R114 R115 R116 R119 R127 R132 R135 R136 R143 R146 R164 R168 R169 R171 R172 R173 R177 R179 R185 R186 R187 R188 R189 R190 R191 R195 R198 R199 R200 R201 R202 R203 R204 R206 R210 R211 R215 R223 R225 R229 R233 R234 R236 R237 R238 R240 R241 R242 R244 R246 R248 R249 R266 R269 R270 R273 R275 R276 R280 R284 R290 R295 R296 R299 R300 R301 R307 R311 R316 R325 R332 R336 R338 R340 R341 R343 R344 R346 R347 R349 R350 R353 R358 R360 R361 R362 R363 R364 R391 R392 R395 R396 R401 R402 R403 R404 R422 R423 R428 R429 R434 R435 R436 R437 R438 R439 R444 R445 R446 R447 R448 R449 R454 R455 R456 R457 R458 R459 R464 R465 R466 R467 R468 R469 R474 R475 R476 R477 R478 R481 R482 R483 R484 R490 R491 R502 R503 R514 R515 R525 R526 R527 R545 R546 R549 R551 R555 R556 U27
